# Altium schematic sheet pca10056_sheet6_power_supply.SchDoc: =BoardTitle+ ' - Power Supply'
size A3; Organization: Nordic Semiconductor; DocumentNumber: 6; SheetNumber: 6; SheetTotal: 6; CompanyName: Nordic Semiconductor; DocumentSize: A3
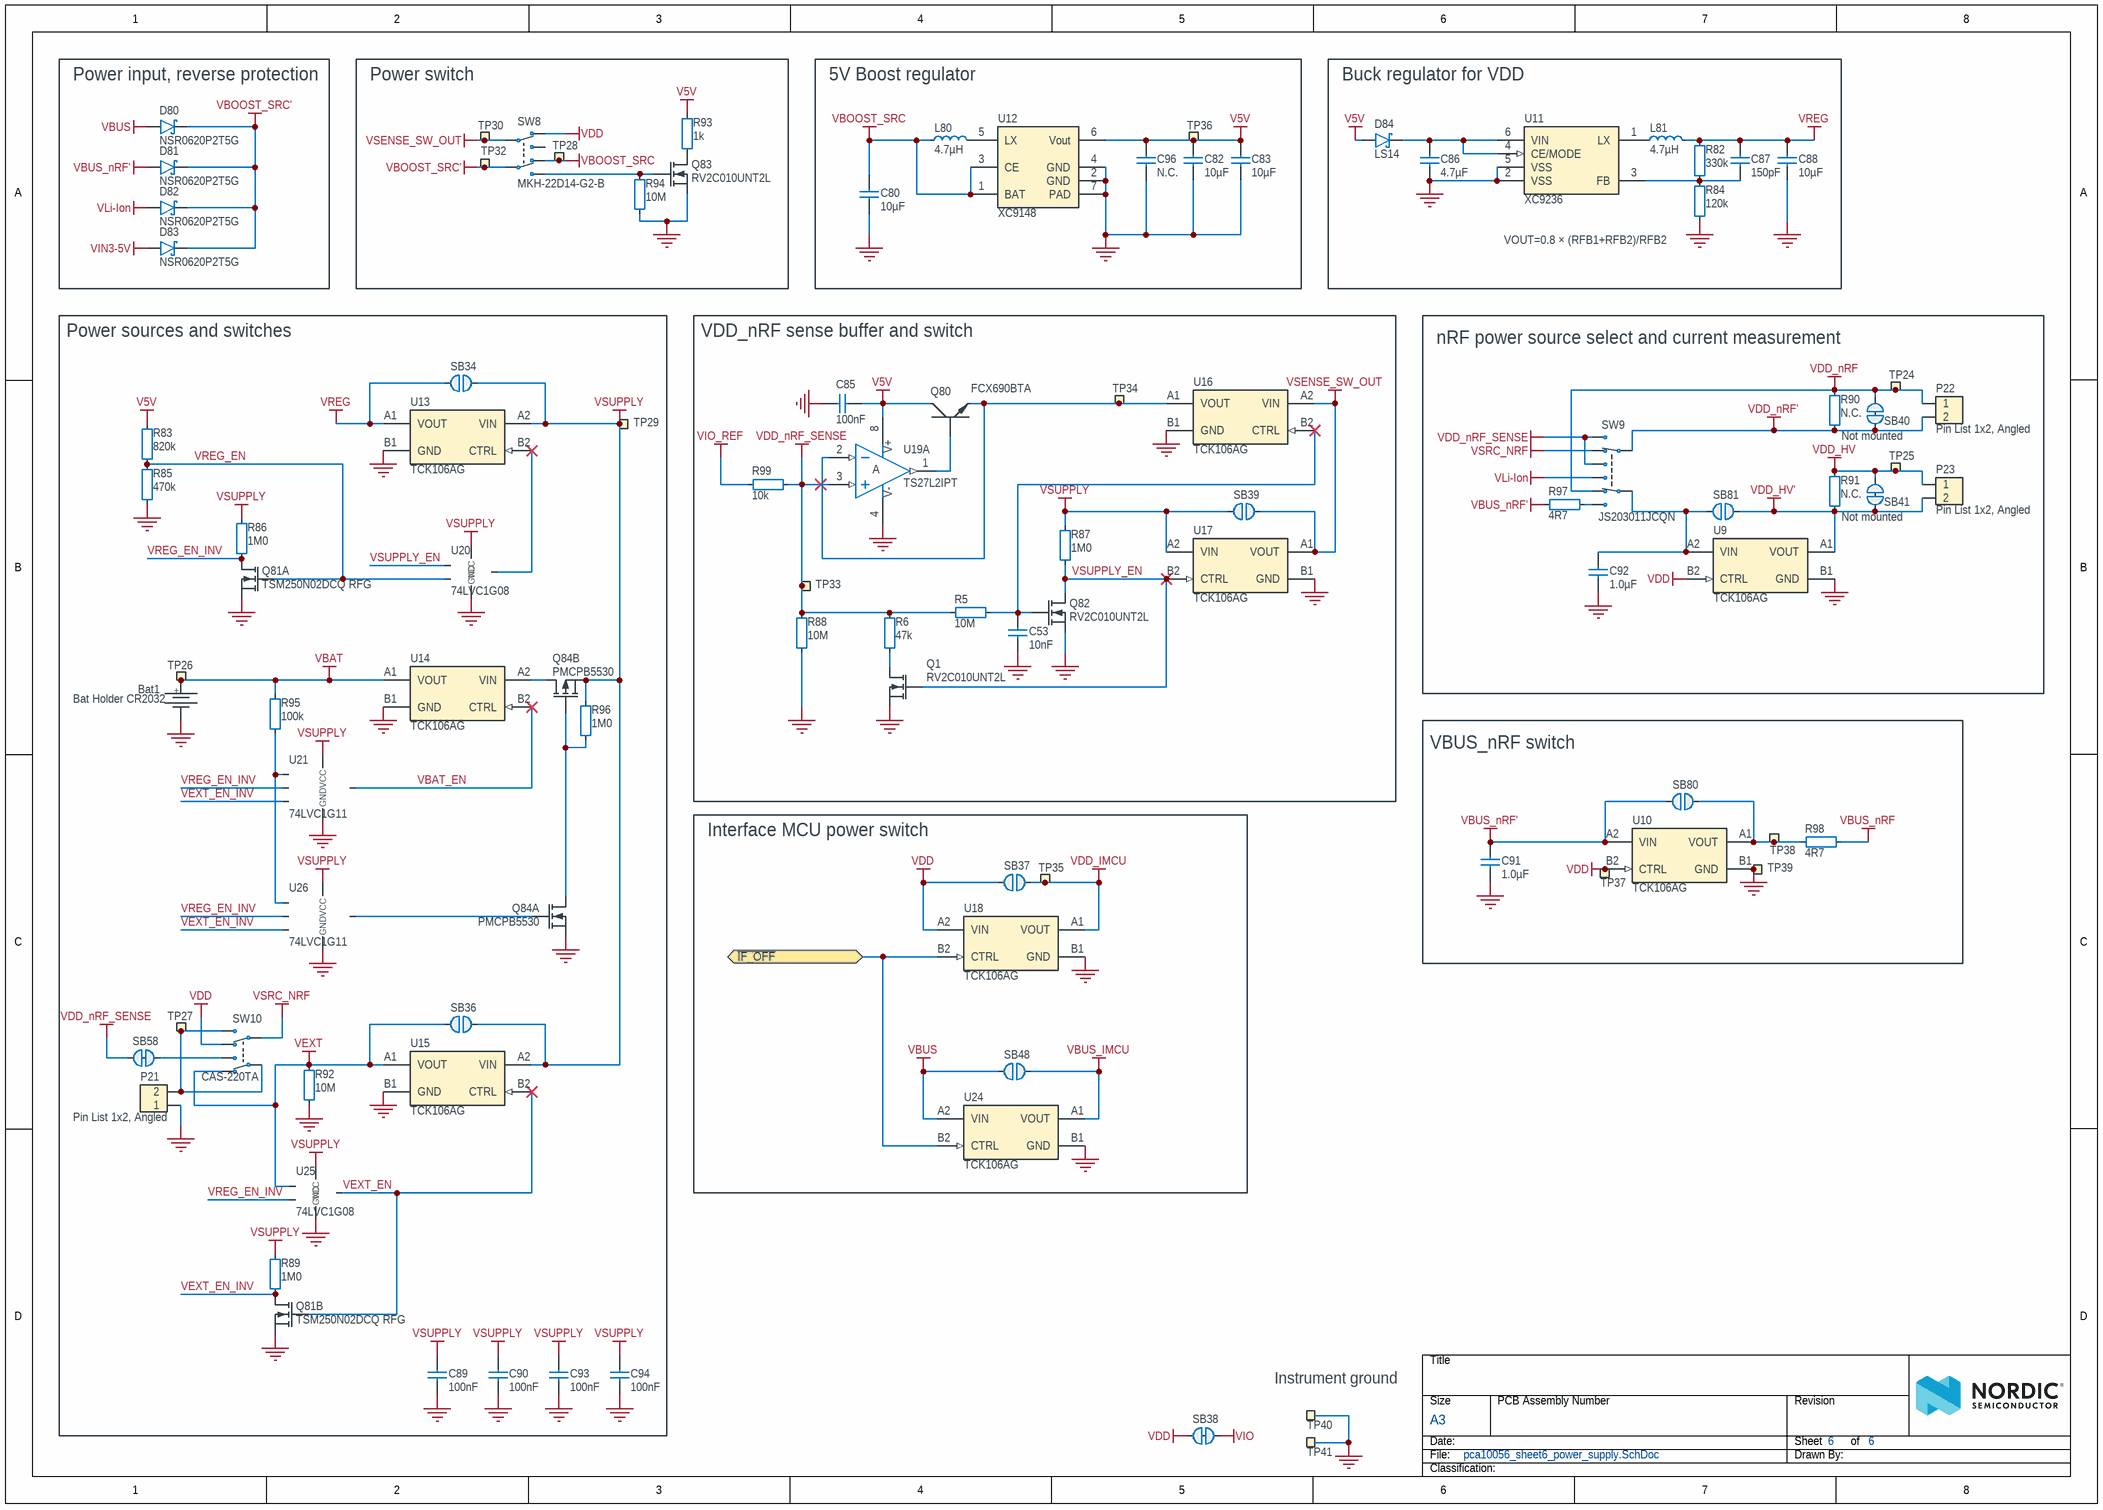
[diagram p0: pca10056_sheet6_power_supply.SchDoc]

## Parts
Bat1  Bat Holder CR2032  [L-KLS5-CR2032-23-B1]
C53  10nF  [CAPC0603X03L_C]
C80  10µF  [CAPC1608X06L]
C82  10µF  [CAPC1608X06L]
C83  10µF  [CAPC1608X06L]
C85  100nF  [CAPC0603X03L_C]
C86  4.7µF  [CAPC2012X11L]
C87  150pF  [CAPC0603X03L_C]
C88  10µF  [CAPC1608X06L]
C89  100nF  [CAPC0603X03L_C]
C90  100nF  [CAPC0603X03L_C]
C91  1.0µF  [CAPC1608X06L]
C92  1.0µF  [CAPC1608X06L]
C93  100nF  [CAPC0603X03L_C]
C94  100nF  [CAPC0603X03L_C]
C96  N.C.  [CAPC1608X06L_NC]
D80  NSR0620P2T5G  [SODFL100X40-2N]
D81  NSR0620P2T5G  [SODFL100X40-2N]
D82  NSR0620P2T5G  [SODFL100X40-2N]
D83  NSR0620P2T5G  [SODFL100X40-2N]
D84  LS14  [SODFL500X108-2N]
L80  4.7µH  [VLS3012HBX]
L81  4.7µH  [TY-NR3015]
P21  Pin List 1x2, Angled  [LIST_ANG_1x2-SMD-2.54MM]
P22  Pin List 1x2, Angled  [LIST_ANG_1x2-SMD-2.54MM]
P23  Pin List 1x2, Angled  [LIST_ANG_1x2-SMD-2.54MM]
Q1  RV2C010UNT2L  [DFN65P100X40-3L]
Q80  FCX690BTA  [SOT89-150P409X160-3N]
Q81  TSM250N02DCQ RFG  [DFN65P200X200X80_HS-6N]  (parts A,B of 2)
Q82  RV2C010UNT2L  [DFN65P100X40-3L]
Q83  RV2C010UNT2L  [DFN65P100X40-3L]
Q84  PMCPB5530  [PMCPB5530X]  (parts A,B of 2)
R5  10M  [RESC0603X03L_C]
R6  47k  [RESC0603X03L_C]
R82  330k  [RESC0603X03L_C]
R83  820k  [RESC0603X03L_C]
R84  120k  [RESC0603X03L_C]
R85  470k  [RESC0603X03L_C]
R86  1M0  [RESC0603X03L_C]
R87  1M0  [RESC0603X03L_C]
R88  10M  [RESC0603X03L_C]
R89  1M0  [RESC0603X03L_C]
R90  N.C.  Assembly: Not mounted  [RESC1005X04L_NC]
R91  N.C.  Assembly: Not mounted  [RESC1005X04L_NC]
R92  10M  [RESC0603X03L_C]
R93  1k  [RESC0603X03L_C]
R94  10M  [RESC0603X03L_C]
R95  100k  [RESC0603X03L_C]
R96  1M0  [RESC0603X03L_C]
R97  4R7  [RESC0603X03L_C]
R98  4R7  [RESC0603X03L_C]
R99  10k  [RESC0603X03L_C]
SB34  Solderbridge  [Solderbridge]  (value not drawn)  (no BOM)
SB36  Solderbridge  [Solderbridge]  (value not drawn)  (no BOM)
SB37  Solderbridge  [Solderbridge]  (value not drawn)  (no BOM)
SB38  Solderbridge  [Solderbridge_Shorted]  (value not drawn)  (net tie, no BOM)
SB39  Solderbridge  [Solderbridge]  (value not drawn)  (no BOM)
SB40  Solderbridge  [Solderbridge_Shorted]  (value not drawn)  (net tie, no BOM)
SB41  Solderbridge  [Solderbridge_Shorted]  (value not drawn)  (net tie, no BOM)
SB48  Solderbridge  [Solderbridge]  (value not drawn)  (no BOM)
SB58  Solderbridge  [Solderbridge_Shorted]  (value not drawn)  (net tie, no BOM)
SB80  Solderbridge  [Solderbridge]  (value not drawn)  (no BOM)
SB81  Solderbridge  [Solderbridge]  (value not drawn)  (no BOM)
SW8  MKH-22D14-G2-B  [MKH-22D14-G2-B]
SW9  JS203011JCQN  [Switch-Slide-J-Lead-DP3T-13x3.5mm]
SW10  CAS-220TA  [CAS-220TA]
TP24  Ø1.0mm,SMD  [TP_SMD_D1.0mm]  (value not drawn)  (no BOM)
TP25  Ø1.0mm,SMD  [TP_SMD_D1.0mm]  (value not drawn)  (no BOM)
TP26  Ø1.0mm,SMD  [TP_SMD_D1.0mm]  (value not drawn)  (no BOM)
TP27  Ø1.0mm,SMD  [TP_SMD_D1.0mm]  (value not drawn)  (no BOM)
TP28  Ø1.0mm,SMD  [TP_SMD_D1.0mm]  (value not drawn)  (no BOM)
TP29  Ø1.0mm,SMD  [TP_SMD_D1.0mm]  (value not drawn)  (no BOM)
TP30  Ø1.0mm,SMD  [TP_SMD_D1.0mm]  (value not drawn)  (no BOM)
TP32  Ø1.0mm,SMD  [TP_SMD_D1.0mm]  (value not drawn)  (no BOM)
TP33  Ø1.0mm,SMD  [TP_SMD_D1.0mm]  (value not drawn)  (no BOM)
TP34  Ø1.0mm,SMD  [TP_SMD_D1.0mm]  (value not drawn)  (no BOM)
TP35  Ø1.0mm,SMD  [TP_SMD_D1.0mm]  (value not drawn)  (no BOM)
TP36  Ø1.0mm,SMD  [TP_SMD_D1.0mm]  (value not drawn)  (no BOM)
TP37  Ø1.0mm,SMD  [TP_SMD_D1.0mm]  (value not drawn)  (no BOM)
TP38  Ø1.0mm,SMD  [TP_SMD_D1.0mm]  (value not drawn)  (no BOM)
TP39  Ø1.0mm,SMD  [TP_SMD_D1.0mm]  (value not drawn)  (no BOM)
TP40  TP  [TESTPAD-TH]  (value not drawn)  (no BOM)
TP41  TP  [TESTPAD-TH]  (value not drawn)  (no BOM)
U9  TCK106AG  [BGA4C40P2X2_76X76X62]
U10  TCK106AG  [BGA4C40P2X2_76X76X62]
U11  XC9236  [USP-6C]
U12  XC9148  [USP-6C]
U13  TCK106AG  [BGA4C40P2X2_76X76X62]
U14  TCK106AG  [BGA4C40P2X2_76X76X62]
U15  TCK106AG  [BGA4C40P2X2_76X76X62]
U16  TCK106AG  [BGA4C40P2X2_76X76X62]
U17  TCK106AG  [BGA4C40P2X2_76X76X62]
U18  TCK106AG  [BGA4C40P2X2_76X76X62]
U19  TS27L2IPT  [TSOP65P640X120-8N]  (part A of 2)
U20  74LVC1G08  [SOT65P210X100-5N]
U21  74LVC1G11  [SOT65P210X100-6N]
U24  TCK106AG  [BGA4C40P2X2_76X76X62]
U25  74LVC1G08  [SOT65P210X100-5N]
U26  74LVC1G11  [SOT65P210X100-6N]

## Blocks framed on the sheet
Power input, reverse protection: D80-D83
Power switch: Q83 R93 R94 SW8 TP28 TP30 TP32
5V Boost regulator: C80 C82 C83 C96 L80 TP36 U12
Buck regulator for VDD: C86-C88 D84 L81 R82 R84 U11
Power sources and switches: Bat1 C89 C90 C93 C94 P21 Q81 Q84 R83 R85 R86 R89 R92 R95 R96 SB34 SB36 SB58 SW10 TP26 TP27 TP29 U13-U15 U20 U21 U25 U26
VDD_nRF sense buffer and switch: C53 C85 Q1 Q80 Q82 R5 R6 R87 R88 R99 SB39 TP33 TP34 U16 U17 U19
nRF power source select and current measurement: C92 P22 P23 R90 R91 R97 SB40 SB41 SB81 SW9 TP24 TP25 U9
VBUS_nRF switch: C91 R98 SB80 TP37-TP39 U10
Interface MCU power switch: SB37 SB48 TP35 U18 U24

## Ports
~{IF_OFF} (bidir)

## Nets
GND: Bat1.2 C53.1 C80.1 C82.1 C83.1 C85.1 C86.1 C88.1 C89.1 C90.1 C91.1 C92.1 C93.1 C94.1 C96.1 P21.1 Q1.2(S) Q81.1(S1) Q81.4(S2) Q82.2(S) Q83.2(S) Q84.1(S1) R84.1 R85.2 R88.2 R92.2 R94.2 TP39.1 TP40.1 TP41.1 U9.B1(GND) U10.B1(GND) U11.2(VSS) U11.5(VSS) U11.7(VSS) U12.2(GND) U12.4(GND) U12.7(PAD) U13.B1(GND) U14.B1(GND) U15.B1(GND) U16.B1(GND) U17.B1(GND) U18.B1(GND) U19.4(V-) U20.3(GND) U21.2(GND) U24.B1(GND) U25.3(GND) U26.2(GND)
V5V: C82.2 C83.2 C85.2 C96.2 D84.2(A) Q80.2(C) R83.1 R93.1 TP36.1 U12.6(Vout) U19.8(V+)
VBAT: Bat1.1 R95.1 TP26.1 U14.A1(VOUT)
VBOOST_SRC: C80.2 L80.1 SW8.6(N.C-2) TP28.1 U12.1(BAT) U12.3(CE)
VBOOST_SRC': D80.1(C) D81.1(C) D82.1(C) D83.1(C) SW8.5(COM-2) TP32.1
VBUS: D80.2(A) SB48.2 U24.A2(VIN)
VBUS_IMCU: SB48.1 U24.A1(VOUT)
VBUS_nRF: R98.2
VBUS_nRF': C91.2 D81.2(A) R97.1 SB80.2 U10.A2(VIN)
VDD: SB37.2 SB38.2 SW8.3(N.C-1) SW10.6(N.C-2) TP37.1 U9.B2(CTRL) U10.B2(CTRL) U18.A2(VIN)
VDD_HV: P23.1 R91.2 SB41.1 TP25.1
VDD_HV': P23.2 R91.1 SB41.2 SB81.1 U9.A1(VOUT)
VDD_IMCU: SB37.1 TP35.1 U18.A1(VOUT)
VDD_nRF: P22.1 R90.2 SB40.1 SW9.6(N.C) TP24.1
VDD_nRF': P22.2 R90.1 SB40.2 SW9.3(COM)
VDD_nRF_SENSE: R5.1 R6.2 R88.1 R99.1 SB58.1 SW9.1(N.O) SW9.4(N.O) TP33.1 U19.3(IN1+)
VEXT: R92.1 SB36.2 SW10.3(N.C-1) U15.A1(VOUT) U25.1(A)
VIN3-5V: D83.2(A)
VIO: SB38.1
VIO_REF: R99.2
VLi-Ion: D82.2(A) SW9.5(N.O)
VREG: C87.2 C88.2 L81.2 R82.2 SB34.2 U13.A1(VOUT)
VSENSE_SW_OUT: SB39.1 SW8.2(COM-1) TP30.1 U16.A2(VIN) U17.A1(VOUT)
VSRC_NRF: SW9.2(N.C) SW10.5(COM-2)
VSUPPLY: C89.2 C90.2 C93.2 C94.2 Q84.4(S2) R86.1 R87.1 R89.1 R96.1 SB34.1 SB36.1 SB39.2 TP29.1 U13.A2(VIN) U15.A2(VIN) U17.A2(VIN) U20.5(VCC) U21.5(VCC) U25.5(VCC) U26.5(VCC)
~{IF_OFF}: U18.B2(CTRL) U24.B2(CTRL) ; port ~{IF_OFF}
VBAT_EN: U14.B2(CTRL) U21.4(Y)
VEXT_EN: Q81.5(G2) U15.B2(CTRL) U25.4(Y)
VEXT_EN_INV: Q81.3(D2) R89.2 U21.6(C) U26.6(C)
VREG_EN: Q81.2(G1) R83.2 R85.1 U20.2(B)
VREG_EN_INV: Q81.6(D1) R86.2 U21.3(B) U25.2(B) U26.3(B)
VSUPPLY_EN: Q1.1(G) Q82.3(D) R87.2 U17.B2(CTRL) U20.1(A)
NetC53_2: C53.2 Q82.1(G) R5.2 U16.B2(CTRL)
NetC86_2: C86.2 D84.1(C) U11.4(CE/MODE) U11.6(VIN)
NetC87_1: C87.1 R82.1 R84.2 U11.3(FB)
NetC92_2: C92.2 SB81.2 SW9.7(COM) U9.A2(VIN)
NetL80_2: L80.2 U12.5(LX)
NetL81_1: L81.1 U11.1(LX)
NetP21_2: P21.2 SW10.2(COM-1) SW10.4(N.O-2) TP27.1
NetQ1_3: Q1.3(D) R6.1
NetQ80_1: Q80.1(B) U19.1(OUT1)
NetQ80_3: Q80.3(E) TP34.1 U16.A1(VOUT) U19.2(IN1-)
NetQ83_1: Q83.1(G) R94.1 SW8.4(N.O-2)
NetQ83_3: Q83.3(D) R93.2
NetQ84_2: Q84.2(G1) U26.4(Y)
NetQ84_3: Q84.3(D2) U14.A2(VIN)
NetQ84_5: Q84.5(G2) Q84.6(D1) R96.2
NetR95_2: R95.2 U21.1(A) U26.1(A)
NetR97_2: R97.2 SW9.8(N.O)
NetR98_1: R98.1 SB80.1 TP38.1 U10.A1(VOUT)
NetSB58_2: SB58.2 SW10.1(N.O-1)
NetU13_B2: U13.B2(CTRL) U20.4(Y)

Not connected (* = marked no-connect by the designer): SW8 1(N.O-1)

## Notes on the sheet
- VOUT=0.8 × (RFB1+RFB2)/RFB2
- (near TP40) Instrument ground

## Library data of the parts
Bat1 = Bat Holder L-KLS5-CR2032-23-B1: Bat Holder CR2032 SMD; Manufacturer: KLS Electronic; Part number NEMS: 100500651; Artikkelnr Noca: N.A.; Pad Count: 2; Component Status: Active; System: Connector
C53 = C0201-10n: Capacitor, X7R, ±10%; Manufacturer: N.A.; Part number IPS: 00000003480; Part number Norautron: 26621779; Part number NEMS: 100200067; Pad Count: 2; Note: 10V; Component Status: Active
C80 C82 C83 C88 = C0603-10µ-25V-X5R-CL10A106MA8NRNC: Capacitor, X5R, ±20%, 25V; Manufacturer: Samsung Electro-Mechanics America; Part number IPS: 00000009948; Part number Norautron: N.A.; Part number NEMS: 100200354; Artikkelnr Noca: 20039436; Pad Count: 2; Component Status: Active
C85 C89 C90 C93 C94 = C0201-100n: Capacitor, X5R, ±10%; Manufacturer: N.A.; Part number IPS: 00000001248, 00000002505; Part number Norautron: 262071862; Part number NEMS: 100200078; Note: 16V; Pad Count: 2; Component Status: Active
C86 = C0805-4µ7: Capacitor, X5R, ±10%, 16V; Manufacturer: N.A.; Part number IPS: 00000006289; Part number NEMS: 100200284; Artikkelnr Noca: 20039266; Pad Count: 2; Component Status: Active
C87 = C0201-150p-25V-COG-GRM0335C1E151JA01D: Capacitor, NP0, ±5%, 25V; Manufacturer: N.A.; Part number IPS: 00000004306; Part number NEMS: 100200444; Note: Chip Cap 5%; Pad Count: 2; Component Status: Active
C91 C92 = C0603-1µ0: Capacitor, X7R, ±10%; Manufacturer: N.A.; Part number IPS: 00000000616; Part number Norautron: 262083409; Part number NEMS: 100200271; Note: 16V; Artikkelnr Noca: 20039282; Pad Count: 2; Component Status: Active
C96 = C0603-N.C.: Not mounted; Manufacturer: N.A.; Part number NEMS: 100200195; Pad Count: 2; Note: Chip Cap; Assembly: Not mounted; Component Status: Active
D80-D83 = NSR0620P2T5G: 20V schottky barrier diode, Vf 350 mV @ 100 mA, Ir 2.0 µA @ 10 V, If 500 mA; Manufacturer: ON Semiconductor; Part number IPS: 00000009952; Part number Norautron: 26311081; Part number NEMS: 101300131; Note: N.A.; Artikkelnr Noca: 10029169; Pad Count: 2; Component Status: Active
D84 = LS14: Diode Schottky Vf=0.45, Vr=40V, If=1A, Ir=1µA; Manufacturer: Good-Ark Semiconductor; Part number NEMS: 101300212; Note: N.A.; Pad Count: 2; Component Status: Active
L80 = VLS3012HBX-4R7M-N: 4.7µH Shielded Wirewound Inductor 2.23A 201 mOhm Max Nonstandard; Manufacturer: TDK Corporation; Part number NEMS: 100300407; Pad Count: 2; Note: N.A.; Component Status: Active
L81 = NR3015-4µ7-1.04A-144mOhm: Ferrite Inductor, Shielded, 1,04A, 144mOhm; Manufacturer: Taiyo Yuden; Manufacturer Part Number: NR3015T4R7M; Part number IPS: 00000009960; Part number NEMS: 100300145; Note: N.A.; Artikkelnr Noca: 33029551; Pad Count: 2; Component Status: Active
P21-P23 = Pin List Ang 1x2 SMD, 2.54mm: Pin List 1x2, 2.54mm (100mil), Right Angled, SMD; Manufacturer: WCON; Manufacturer Part Number: 1125B-1102S0Z135CR06; Part number NEMS: 100500354; Note: (Replaced 1125B-1102S0Z135R2); Artikkelnr Noca: N.A.; Pad Count: 2; Component Status: Active; System: Connector
Q1 = RV2C010UNT2L: N-Channel MOSFET, 20V, 1A, 470mOhm, 400mW; Manufacturer: Rohm Semiconductor; Part number IPS: 00000009976; Part number Norautron: 26320026; Part number NEMS: 101300132; Pad Count: 3; Note: N.A.; Artikkelnr Noca: 35010020; Component Status: Active
Q80 = FCX690BTA: 45V NPN high gain power transistor; Manufacturer: Diodes Incorporated; Part number IPS: 00000009974; Part number NEMS: 101300130; Note: N.A.; Artikkelnr Noca: 35010019; Pad Count: 3; Component Status: Active
Q81 = TSM250N02DCQ RFG: Dual N Ch MOFET, 5.8A, 55mOhm max, 620mW; Manufacturer: Taiwan Semiconductor; Part number IPS: 00000001703; Part number NEMS: 101300161; Note: N.A.; Pad Count: 6; Component Status: Active
Q82 Q83 = RV2C010UNT2L: N-Channel MOSFET, 20V, 1A, 470mOhm, 400mW; Manufacturer: Rohm Semiconductor; Part number IPS: 00000009976; Part number Norautron: 26320026; Part number NEMS: 101300132; Note: N.A.; Artikkelnr Noca: 35010020; Pad Count: 3; Component Status: Active
Q84 = PMCPB5530X,115: Mosfet Array N and P-Channel 20V 4A (Ta), 3.4A (Ta) 490mW Surface Mount 6-HUSON-EP (2x2); Manufacturer: Nexperia; Part number IPS: 00000001918; Part number NEMS: 101300165; Note: N.A.; Pad Count: 8; Component Status: Active
R5 = R0201-10M: Resistor, ±1%, 0.05W; Manufacturer: N.A.; Part number IPS: 00000001426; Part number NEMS: 100100105; Pad Count: 2; Note: Chip Res 1%; Component Status: Active
R6 = R0201-47k: Resistor, ±1%, 0.05W; Manufacturer: N.A.; Part number IPS: 00000001423; Part number NEMS: 100100076; Pad Count: 2; Note: Chip Res 1%; Component Status: Active
R82 = R0201-330k: Resistor, ±1%, 0.05W; Manufacturer: N.A.; Part number IPS: 00000001424; Part number NEMS: 100100087; Note: Chip Res 1%; Pad Count: 2; Component Status: Active
R83 = R0201-820k: Resistor, ±1%, 0.05W; Manufacturer: N.A.; Part number IPS: 00000001427; Part number NEMS: 100100092; Note: Chip Res 1%; Pad Count: 2; Component Status: Active
R84 = R0201-120k: Resistor, ±1%, 0.05W; Manufacturer: N.A.; Part number IPS: 00000001425; Part number NEMS: 100100081; Note: Chip Res 1%; Pad Count: 2; Component Status: Active
R85 = R0201-470k: Resistor, ±1%, 0.05W; Manufacturer: N.A.; Part number IPS: 00000001428; Part number NEMS: 100100089; Note: Chip Res 1%; Pad Count: 2; Component Status: Active
R86 R87 R89 R96 = R0201-1M0: Resistor, ±1%, 0.05W; Manufacturer: N.A.; Part number IPS: 00000001418; Part number Norautron: 26107108; Part number NEMS: 100100093; Note: Chip Res 1%; Pad Count: 2; Component Status: Active
R88 R92 R94 = R0201-10M: Resistor, ±1%, 0.05W; Manufacturer: N.A.; Part number IPS: 00000001426; Part number NEMS: 100100105; Note: Chip Res 1%; Pad Count: 2; Component Status: Active
R90 R91 = R0402-N.C.: Not mounted; Manufacturer: N.A.; Part number NEMS: 100100281; Note: Chip Res; Pad Count: 2; Component Status: Active
R93 = R0201-1k0: Resistor, ±1%, 0.05W; Manufacturer: N.A.; Part number IPS: 00000005786; Part number NEMS: 100100043; Note: Chip Res 1%; Pad Count: 2; Component Status: Active
R95 = R0201-100k: Resistor, ±1%, 0.05W; Manufacturer: N.A.; Part number IPS: 00000001419; Part number Norautron: 26108487; Part number NEMS: 100100080; Note: Chip Res 1%; Pad Count: 2; Component Status: Active
R97 R98 = R0201-4R7: Resistor, ±1%, 0.05W; Manufacturer: N.A.; Part number IPS: 00000002486; Part number NEMS: 100100010; Note: Chip Res 1%; Pad Count: 2; Component Status: Active
R99 = R0201-10k: Resistor, ±1%, 0.05W; Manufacturer: N.A.; Part number IPS: 00000001255; Part number Norautron: 26107101; Part number NEMS: 100100065; Note: Chip Res 1%; Pad Count: 2; Component Status: Active
SB34 SB36 SB37 SB39 SB48 SB80 SB81 = Solderbridge: Manufacturer: N.A.; Part number NEMS: 100500458; Pad Count: 2; Component Status: Active; System: Connector
SB38 SB40 SB41 SB58 = Solderbridge Shorted: Shorted Solderbridge; Manufacturer: N.A.; Part number NEMS: 100500459; Pad Count: 2; Component Status: Active; System: Connector
SW8 = MKH-22D14-G2-B: Slide Switch DPDT; Manufacturer: Dailywell; Part number IPS: 00000004369; Part number NEMS: 101500096; Note: N.A.; Artikkelnr Noca: 50019112; Pad Count: 6; Component Status: Active
SW9 = JS203011JCQN: Slide Switch DP3T 300mA 6V; Manufacturer: C&K; Part number IPS: 00000004321; Part number NEMS: 101500099; Note: N.A.; Artikkelnr Noca: 50019116; Pad Count: 8; Component Status: Active
SW10 = CAS-220TA: Slide Switch DPDT J Hook; Manufacturer: Copal Electronics Inc; Part number IPS: 00000009983; Part number NEMS: 101500003; Note: N.A.; Artikkelnr Noca: 50019042; Pad Count: 6; Component Status: Active
TP24-TP30 TP32-TP39 = TP_SMD_Ø1.0MM: 1.0mm circular SMD testpad; Manufacturer: Nordic Semiconductor; Manufacturer Part Number: N.A.; Part number NEMS: 100500475; Pad Count: 1; Component Status: Active
TP40 TP41 = Testpoint TH: Testpoint, through hole; Manufacturer: N.A.; Part number NEMS: 100500464; Pad Count: 1; Component Status: Active
U9 U10 = TCK106AG: 1.0 A Load Switch IC with Slew Rate Control Driver in Ultra Small Package; Manufacturer: Toshiba; Manufacturer Part Number: TCK106AG,LF; Part number IPS: 00000004390; Part number Norautron: 26500627; Part number NEMS: 101900575; Pad Count: 4; Note: N.A.; Component Status: Active
U11 = XC9236D08CER-G: 600mA Driver Transistor Built-In, Synchronous Step-Down DC/DC Converters; Manufacturer: Torex Semiconductor; Part number IPS: 00000004325; Part number NEMS: 101900207; Note: N.A.; Artikkelnr Noca: 17030085; Pad Count: 6; Component Status: Active
U12 = XC9148A50CER-G: 1.4A Driver Transistor Built-In, Multi Functional Step-Up DC/DC Converter; Manufacturer: Torex Semiconductor; Part number NEMS: 101900670; Pad Count: 6; Note: N.A.; Component Status: Active
U13-U18 U24 = TCK106AG: 1.0 A Load Switch IC with Slew Rate Control Driver in Ultra Small Package; Manufacturer: Toshiba; Manufacturer Part Number: TCK106AG,LF; Part number IPS: 00000004390; Part number Norautron: 26500627; Part number NEMS: 101900575; Note: N.A.; Pad Count: 4; Component Status: Active
U19 = TS27L2IPT: Precision very low power CMOS dual operational amplifier; Manufacturer: STMicroelectronics; Part number IPS: 00000009991; Part number NEMS: 101900442; Note: N.A.; Artikkelnr Noca: 17010019; Pad Count: 8; Component Status: Active
U20 U25 = 74LVC1G08GW: Single 2-Input AND Gate; Manufacturer: NXP Semiconductors; Part number IPS: 00000009992; Part number Norautron: N.A.; Part number NEMS: 101900155; Artikkelnr Noca: 15049058; Pad Count: 5; Component Status: Active
U21 U26 = 74LVC1G11GW: Single 3-input AND gate; Manufacturer: NXP Semiconductors; Part number IPS: 00000001430; Part number Norautron: N.A.; Part number NEMS: 101900157; Artikkelnr Noca: 15079348; Pad Count: 6; Component Status: Active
